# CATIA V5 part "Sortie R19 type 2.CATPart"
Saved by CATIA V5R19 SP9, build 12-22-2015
Part number: Sortie
Bounding box of the stored display mesh (mm): x -29 to 13.996, y 0 to 25.5, z -13.996 to 13.996
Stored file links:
  C:\Users\hbezard\Documents\Perso\imprimante 3d\pieces\rincepot\Sortie R19 type 2.CATPart
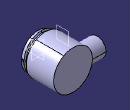
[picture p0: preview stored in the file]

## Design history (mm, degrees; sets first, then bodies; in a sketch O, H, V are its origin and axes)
Parameters
  `dia admi` = 22
  `dia evac` = 10
  `paroies hp` = 2
  `paroies bp` = 2
  `longueur filetee` = 5
  `pas jonction` = 2
  `prof filet jonction` = 1
  `dia gourde` = 12
  `pas gourde` = 2
  `entree gourde` = 8
  `longueur jonction` = 30
  `dia injection` = 8
  `longueur injection` = 110
  `longueur gourde` = 30
  `dia inter injection` = 6
  Real = 0
Body1 (main body)
  Sketch1 on yz-plane, origin (0, 0, 0), H (0, 1, 0), V (0, 0, 1)
    line L1 (0, 5) -> (0, 6)
    line L2 (0, 6) -> (5.5, 6)
    line L3 (5.5, 6) -> (5.5, 8)
    line L4 (5.5, 8) -> (21.5, 8)
    line L5 (25.5, 0) -> (9, 0)
    line L6 (9, 0) -> (9, 5)
    line L7 (9, 5) -> (0, 5)
    reference intersected line E1 through (0, 0) direction (0, 1) from zx-plane
    axis line L8 (-32.3822, 0) -> (183.7177, 0)
    line L9 (0, 11) -> (0, 12)
    line L10 (0, 12) -> (5.5, 12)
    line L11 (5.5, 14) -> (25.5, 14)
    line L12 (25.5, 14) -> (25.5, 0)
    line L13 (21.5, 11) -> (0, 11)
    line L14 (5.5, 12) -> (5.5, 14)
    line L15 (21.5, 8) -> (21.5, 11)
    point P15 (-31.9622, 57.8884)
    reference intersected line E2 through (0, 0) direction (-1, 0) from xy-plane
    reference intersected line E3 through (0, 0) direction (0, 1) from zx-plane
    distance L2 L7 = 1
    distance L7 L8 = 5
    angle L2 L3 = 90
    length L2 = 5.5
    distance L10 L13 = 1
    length L10 = 5.5
    distance L13 L8 = 11
    distance L4 L8 = 8
    distance L11 L8 = 14
    distance L6 E3 = 9
    distance L15 L12 = 4
    distance L14 L12 = 20
    vertical: L1 V, L9 V, L12 V
    horizontal: L2 H, L4 H, L5 H, L7 H, L8 H, L10 H, L11 H, L13 H
    coincidence: L1 E1, L9 E1, L8 E2, L5 L8
  Shaft1 "jonction": profile Sketch1, axis Sketch1.L8, angle 360
  Plane1: type Offset, RefPlane xy-plane, Offset 20
  Sketch2 on Plane1, origin (0, 0, 20), H (1, 0, 0), V (0, 1, 0)
    circle A1 centre (0, 15) radius 7.5
    point P1 (0, 15)
    reference intersected line E1 through (0, 0) direction (0, 1) from yz-plane
    reference intersected line E2 through (0, 0) direction (-1, 0) from zx-plane
    distance P1 E2 = 15
    radius A1 = 7.5
    coincidence: P1 E1
  Pad1 "gourde": profile Sketch2, direction (0, 0, -1), up to face of Shaft1 from Sketch1.L11, deactivated
  Sketch3 on Plane1, origin (0, 0, 20), H (1, 0, 0), V (0, 1, 0)
    point P1 (0, 15)
    reference intersected line E1 through (0, 0) direction (0, 1) from yz-plane
    reference intersected line E2 through (0, 0) direction (-1, 0) from zx-plane
    circle A1 centre (0, 15) radius 3
    distance P1 E2 = 15
    radius A1 = 3
    coincidence: P1 E1
  Pocket1: profile a sketch, direction (0, 0, -1), up to face of Shaft1 from Sketch1.L13, deactivated
  Pad2: profile Sketch3, direction (0, 0, -1), up to face of Shaft1 from Sketch1.L4, opposite side length 100, deactivated
  Sketch4 on Plane1, origin (0, 0, 20), H (1, 0, 0), V (0, 1, 0)
    circle A1 centre (0, 15) radius 2
    reference projected point E1 (0, 15) from axis of face of Pad2 from Sketch3.A1
    reference projected circle E2 centre (0, 15) radius 3 from Sketch3.A1
    distance A1 E2 = 1
    concentricity: A1 E1
  Pocket2: profile Sketch4, direction (0, 0, -1), through (limit type 6), opposite side length 98, deactivated
  Plane2: type Angle, RefPlane yz-plane, Direction Y axis, Angle -30
  Plane3: type Offset, RefPlane {inverselocal InverseElem Plane2}, Offset 10, reversed
  Sketch5 on Plane3, origin (-4.0798, 0, 27.0665), H (0, -1, 0), V (-0.5, 0, 0.866)
    line L1 (-7, -23.9802) -> (-5.6623, -23.9802)
    line L2 (-5.6623, -23.9802) -> (-5.6623, -26.9802)
    line L3 (-5.6623, -26.9802) -> (-7, -26.9802)
    line L4 (-7, -26.9802) -> (-7, -23.9802)
    reference intersected line E1 through (0, 0) direction (0, -1) from face of Shaft1 from Sketch1.L9
    length L3 = 1.3377 {= `détruit_LENGTH`}
    distance L4 E1 = 7
    horizontal: L1 H, L3 H
    vertical: L2 V, L4 V
  Pad3: profile Sketch5, direction (-0.866, 0, -0.5), up to face of Shaft1 from Sketch1.L4, opposite side up to face of Shaft1 from Sketch1.L13, deactivated
  Mirror1: of Pad3, about yz-plane, deactivated
  Plane4: type Offset, RefPlane xy-plane, Offset 10, reversed
  Sketch6 on Plane4, origin (0, 0, -10), H (1, 0, 0), V (0, 1, 0)
    point P1 (0, 8)
    line L1 (1, 10) -> (1, 6)
    line L2 (1, 6) -> (-1, 6)
    line L3 (-1, 6) -> (-1, 10)
    line L4 (-1, 10) -> (1, 10)
    reference projected line E1 through (0, 0) direction (0, 1) from axis of face of Shaft1 from Sketch1.L7
    reference intersected line E2 through (0, 0) direction (-1, 0) from face of Shaft1 from Sketch1.L9
    length L3 = 4
    length L4 = 2
    distance L2 E2 = 6
    vertical: L1 V, L3 V
    horizontal: L2 H, L4 H
    equidistance: L1 L3 P1, L2 L4 P1
    coincidence: P1 E1
  Pad4: profile Sketch6, direction (0, 0, 1), up to face of Shaft1 from Sketch1.L4, opposite side up to face of Shaft1 from Sketch1.L13, deactivated
  Fillet1: radius 0.5, on face of Pad4 from Sketch6.L2; face of Pad4 from Sketch6.L1; face of Pad4 from Sketch6.L3; face of Pad4 from Sketch6.L4; face of Pad4 (x4), deactivated
  Fillet2: radius 0.5, on face of Pad3 from Sketch5.L4; face of Pad3 from Sketch5.L3; face of Pad3 from Sketch5.L1; face of Pad3 from Sketch5.L2; face of Pad3 (x4); face of Mirror1 (x8), deactivated
  Fillet3: radius 0.5, on edge [face of Shaft1 from Sketch1.L4 | face of Pad2 from Sketch3.A1], deactivated
  Fillet4: radius 0.5, on edge [face of Pad1 from Sketch2.A1 | face of Shaft1 from Sketch1.L11], deactivated
  Point1: type Center, Curve edge [face of Shaft1 from Sketch1.L12 | face of Shaft1]
  Helix1: Direction Y axis, RefPoint {point type Coord, X 0, Y -1.155, Z 0, RefPoint vertex [element of Sketch1 | element of Sketch1]}, Pitch 2, Height 3.5, TaperAngle 0
  Sketch7 on yz-plane, origin (0, 0, 0), H (0, 1, 0), V (0, 0, 1)
    point P1 (3.7679, 12)
    line L1 (3.7679, 12) -> (4.9226, 12)
    point P2 (4.9226, 12)
    line L2 (4.9226, 12) -> (4.3453, 13)
    point P3 (4.3453, 13)
    line L3 (4.3453, 13) -> (3.7679, 12)
    axis line L4 (4.3453, 15.5745) -> (4.3453, 9.1301)
    reference projected line E1 (5.5, 12) -> (0, 12) from Sketch1.L10
    reference projected line E2 (5.5, 14) -> (5.5, -14) from edge [face of Shaft1 from Sketch1.L14 | face of Shaft1 from Sketch1.L11]
    length L4 = 6.4444
    angle L2 L1 = 60
    distance L1 P3 = 1
    distance L1 E1 = 0
    distance L4 E2 = 1.1547 {= Sketch7.length(L1)}
    length L1 = 1.1547 (reference)
    horizontal: L1 H
    vertical: L4 V
    symmetry: P2 P1 L4
    coincidence: P3 L4
  Rib1: profile Sketch7, centre curve Helix1
  Fillet5: radius 0.5, on face of Rib1, deactivated
  Fillet6: radius 0.5, on face of Rib1
  Helix2: Direction Y axis, RefPoint vertex [element of Sketch1 | element of Sketch1], Pitch 2, Height 4, TaperAngle 0
  Sketch8 on yz-plane, origin (0, 0, 0), H (0, 1, 0), V (0, 0, 1)
    point P1 (0, 6)
    line L1 (0, 6) -> (1.1547, 6)
    point P2 (1.1547, 6)
    line L2 (1.1547, 6) -> (0.5774, 7)
    point P3 (0.5774, 7)
    line L3 (0.5774, 7) -> (0, 6)
    axis line L4 (0.5774, 18.6338) -> (0.5774, 12.1894)
    reference projected point E1 (0, 6) from vertex [element of Sketch1 | element of Sketch1]
    length L4 = 6.4444
    angle L2 L1 = 60
    distance L1 P3 = 1
    horizontal: L1 H
    vertical: L4 V
    symmetry: P2 P1 L4
    coincidence: P3 L4, P1 E1
  Rib2: profile Sketch8, centre curve Helix2
  Fillet7: radius 0.5, on face of Rib2
  Fillet8: radius 0.5, on face of Rib2
  Sketch9 on yz-plane, origin (0, 0, 0), H (0, 1, 0), V (0, 0, 1)
    point P1 (25.5, 0)
    line L1 (25.5, 0) -> (24.3453, 0)
    point P2 (24.3453, 0)
    line L2 (24.3453, 0) -> (24.9226, -1)
    point P3 (24.9226, -1)
    line L3 (24.9226, -1) -> (25.5, 0)
    axis line L4 (24.9226, 19.8788) -> (24.9226, 13.4344)
    reference projected point E1 (25.5, 0) from vertex [element of Sketch1 | element of Sketch1]
    length L4 = 6.4444
    angle L2 L1 = 60
    distance L1 P3 = 1
    horizontal: L1 H
    vertical: L4 V
    symmetry: P2 P1 L4
    coincidence: P3 L4, P1 E1
  Sketch10 on yz-plane, origin (0, 0, 0), H (0, 1, 0), V (0, 0, 1)
    point P1 (15, 0)
    line L1 (15, 0) -> (13.8453, 0)
    point P2 (13.8453, 0)
    line L2 (13.8453, 0) -> (14.4226, -1)
    point P3 (14.4226, -1)
    line L3 (14.4226, -1) -> (15, 0)
    axis line L4 (14.4226, 13.8788) -> (14.4226, 7.4344)
    reference projected point E1 (15, 0) from vertex [element of Sketch1 | element of Sketch1]
    length L4 = 6.4444
    angle L2 L1 = 60
    distance L1 P3 = 1
    horizontal: L1 H
    vertical: L4 V
    symmetry: P2 P1 L4
    coincidence: P3 L4, P1 E1
  Helix3: Direction Y axis, RefPoint vertex [element of Sketch1 | element of Sketch1], Pitch 2, Height 4, TaperAngle 0
  Helix4: Direction Y axis, RefPoint vertex [element of Sketch1 | element of Sketch1], Pitch 2, Height 4, TaperAngle 0
  Rib3: profile Sketch9, centre curve Helix3, deactivated
  Rib4: profile Sketch10, centre curve Helix4, deactivated
  Fillet9: radius 0.5, on face of Rib3, deactivated
  Fillet10: radius 0.5, on face of Rib4, deactivated
  Fillet11: radius 0.5, on face of Rib4, deactivated
  Fillet12: radius 0.5, on face of Rib3, deactivated
  Sketch11 on start face of Pad2, origin (0, 0, 120), H (1, 0, 0), V (0, 1, 0)
    point P1 (0, 0)
  Hole1: placed by Sketch11, at (0, 15, 120) direction (0, 0, -1), diameter 1, through (limit type 6), deactivated
  Point2: type OnCurve, Support edge [face of Pad2 from Sketch3.A1 | start face of Pad2], RefPoint {extremum Reference edge [face of Pad2 from Sketch3.A1 | start face of Pad2], Direction (1, 2, 3)}, Ratio 0.5
  Helix5: Direction {line type PtDir, RefPoint {point type Center, Curve edge [face of Pad2 from Sketch3.A1 | start face of Pad2]}, Direction start face of Pad2, Start 0, End 20}, RefPoint {point type OnCurve, Support a sketch, RefPoint {extremum Reference a sketch, Direction (1, 2, 3)}, Ratio 0.5}, Pitch 2, Height 5, TaperAngle 0
  Sketch12 on yz-plane, origin (0, -0.7113, -0.4445), H (0, 1, 0), V (0, 0, 1)
    point P1 (15.7113, 116.4445)
    reference projected line E1 through (15.7113, 0) direction (0, 1) from axis of face of Pad2 from Sketch3.A1
    reference intersected line E2 (12.7113, 120.4445) -> (18.7113, 120.4445) from start face of Pad2
    distance P1 E2 = 4
    coincidence: P1 E1
  Hole2: placed by Sketch12, at (0, 15, 116) direction (-1, 0, 0), diameter 1, through (limit type 3), deactivated
  CircPattern1: of Hole2, instances 8, angular step 45, axis from {line type PtDir, RefPoint {point type Center, Curve edge [face of Pad2 from Sketch3.A1 | start face of Pad2]}, Direction start face of Pad2, Start 0, End 20}, deactivated
  RectPattern1: of CircPattern1, direction 1 instances 10, spacing 9, along Z axis reversed, deactivated
  Plane5: type Normal, Curve edge [start face of Pad1 | face of Pocket1], RefPoint vertex of Helix5
  Sketch13 on Plane5, origin (-6.7082, 1.5836, 0), H (0.4472, 0.8944, 0), V (0, 0, 1)
    point P1 (8.5, 20)
    line L1 (8.5, 20) -> (8.5, 18.8453)
    point P2 (8.5, 18.8453)
    line L2 (8.5, 18.8453) -> (9.5, 19.4226)
    point P3 (9.5, 19.4226)
    line L3 (9.5, 19.4226) -> (8.5, 20)
    axis line L4 (6.1394, 19.4226) -> (12.5838, 19.4226)
    point P4 (6.1394, 19.4226)
    reference projected point E1 (8.5, 20) from vertex of Helix5
    length L4 = 6.4444
    angle L2 L1 = 60
    distance L1 P3 = 1
    distance L1 P4 = 2.3606
    symmetry: P2 P1 L4
    coincidence: P3 L4, P1 E1
    perpendicularity: L4 L1
    vertical: L1 V
  Rib5: profile Sketch13, centre curve Helix5, deactivated
  Sketch14 on face of Shaft1 from Sketch1.L15, origin (0, 23.9031, 0), H (1, 0, 0), V (0, 0, 1)
    point P1 (0, -6)
    reference intersected line E1 through (0, 0) direction (0, 1) from yz-plane
    reference projected circle E2 centre (0, 0) radius 11 from edge [face of Shaft1 from Sketch1.L15 | face of Shaft1 from Sketch1.L13]
    distance P1 E1 = 0
    distance P1 E2 = 5
  Hole3: placed by Sketch14, at (0, 23.9031, -6) direction (0, 1, 0), diameter 10, through (limit type 3), deactivated
  Sketch15 on face of Shaft1 from Sketch1.L12, origin (0, 30, 14), H (1, 0, 0), V (0, 0, -1)
    projected circle E1 centre (0, 20) radius 5 from edge [face of Shaft1 from Sketch1.L12 | face of Hole3]
  Pad5: profile Sketch15, direction (0, 1, 0), length 10, thin wall 0, second thickness 1, deactivated
  Plane6: type Offset, RefPlane yz-plane, Offset 18, reversed
  Sketch16 on Plane6, origin (-18, 0, 0), H (0, 1, 0), V (0, 0, 1)
    circle A1 centre (14, -5.5) radius 5.5
    point P1 (14, -5.5)
    reference projected line E1 through (0, 0) direction (1, 0) from axis of face of Shaft1 from Sketch1.L13
    reference projected line E2 (5.5, 14) -> (5.5, -14) from edge [face of Shaft1 from Sketch1.L14 | face of Shaft1 from Sketch1.L11]
    radius A1 = 5.5
    distance P1 E1 = 5.5
    distance A1 E2 = 3
  Pocket3: profile Sketch16, direction (-1, 0, 0), through (limit type 6)
  Sketch17 on Plane6, origin (-18, 0, 0), H (0, 1, 0), V (0, 0, 1)
    projected circle E1 centre (14, -5.5) radius 5.5 from edge [face of Pocket3 from Sketch16.A1 | face of Shaft1 from Sketch1.L11]
  Pad6: profile Sketch17, direction (1, 0, 0), up to the existing solid (limit type 2), opposite side length 11, thin wall 0, second thickness 1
